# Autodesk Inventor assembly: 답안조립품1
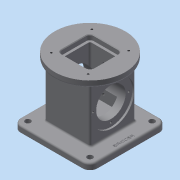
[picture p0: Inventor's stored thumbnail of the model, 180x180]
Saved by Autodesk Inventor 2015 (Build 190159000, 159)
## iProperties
Created: 2021-05
Part Number: 답안조립품1
Document SubType Name: Assembly
Designer: 101258642
Author: 101258642
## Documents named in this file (2)
- C:\Users\101258642\Desktop\710506V1010\답안조립품1.iam
- C:\Users\101258642\Desktop\710506V1010\본체.ipt
